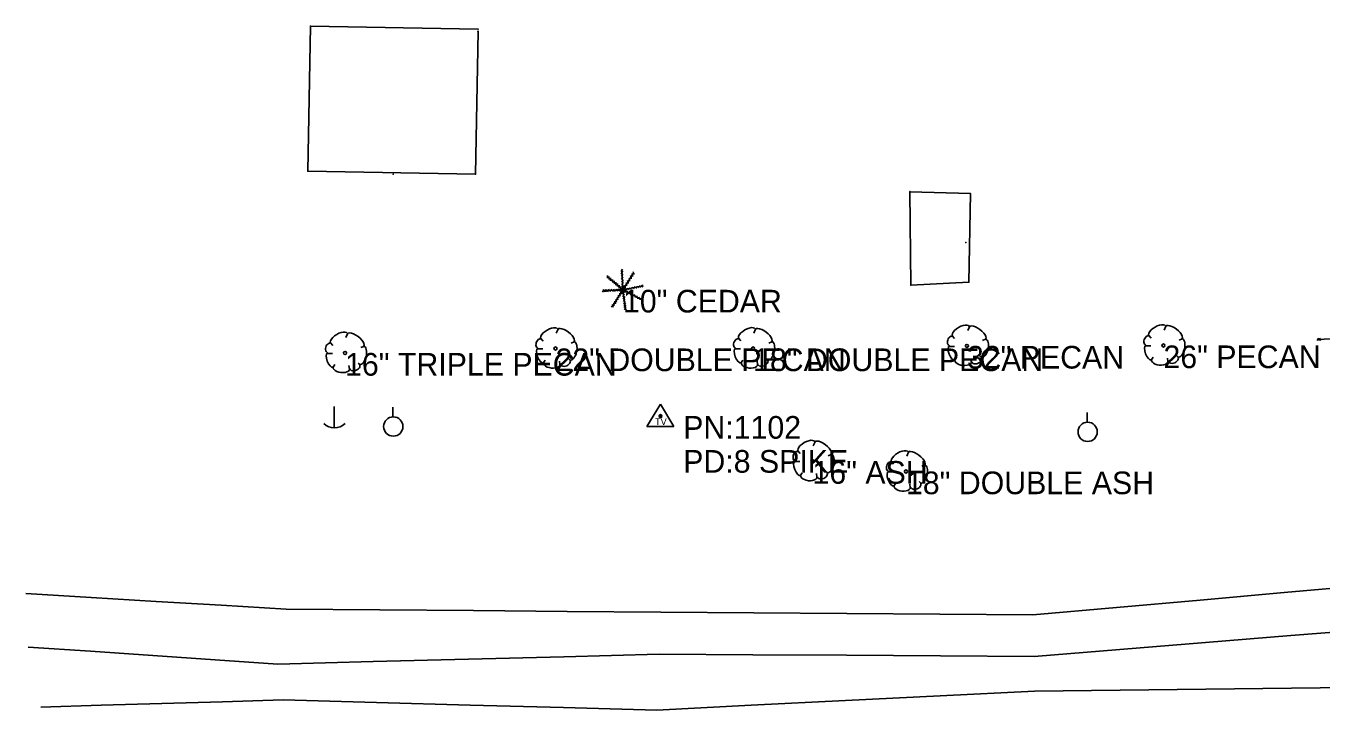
# Model space of a CAD drawing. Extents: x 1930288 to 1941089, y 588389 to 611475.
# Drawn here: x 1930358.9 to 1930644.9, y 598182.4 to 598333.3 of the extents above; entities that cross this region are included whole.
import ezdxf

# ---------------------------------------------------------------- set-up
doc = ezdxf.new("R2010")
doc.units = 0
for name, color, linetype in [('S_BUILDING', 7, 'Continuous'), ('S_DITCHLINE', 7, 'Continuous'), ('S_MSC_PT_SYM', 7, 'Continuous'), ('S_SECONDARY_CTL', 7, 'Continuous'), ('S_SECONDARY_CTL_ANNOT', 7, 'Continuous'), ('S_STR_PT_SYM', 7, 'Continuous'), ('S_STREAM', 7, 'Continuous'), ('S_TREE', 7, 'Continuous'), ('S_TREE_ANNOT', 7, 'Continuous'), ('S_UTILITY_POLE', 7, 'Continuous')]:
    doc.layers.add(name, color=color, linetype=linetype)

msp = doc.modelspace()

# ---------------------------------------------------------------- linework, layer by layer
at = {"layer": 'S_BUILDING'}
for p, q in [((1930421.19, 598301.28), (1930421.76, 598333.27)), ((1930421.76, 598333.27), (1930458.76, 598332.62)), ((1930458.75, 598332.12), (1930458.19, 598300.62)), ((1930458.19, 598300.62), (1930421.19, 598301.28)), ((1930567.44, 598296.33), (1930554.09, 598296.75)), ((1930554.09, 598296.75), (1930554.28, 598276.12)), ((1930567.08, 598276.78), (1930567.44, 598296.33)), ((1930554.28, 598276.12), (1930567.08, 598276.78))]:
    msp.add_line(p, q, dxfattribs=at)
at = {"layer": 'S_DITCHLINE'}
msp.add_lwpolyline([(1930657.08, 598200.36), (1930638.19, 598198.83), (1930619.3, 598197.31), (1930600.42, 598195.78), (1930581.53, 598194.26), (1930560.82, 598194.37), (1930540.12, 598194.49), (1930519.42, 598194.6), (1930498.71, 598194.71), (1930477.66, 598194.18), (1930456.61, 598193.64), (1930435.57, 598193.1), (1930414.52, 598192.57), (1930400.74, 598193.5), (1930386.97, 598194.44), (1930373.2, 598195.37), (1930359.42, 598196.3)], dxfattribs=at)
at = {"layer": 'S_MSC_PT_SYM'}
for points in [[(1930440.04, 598300.62), (1930440.04, 598300.67), (1930440.04, 598300.62), (1930439.99, 598300.62), (1930440.04, 598300.62), (1930440.04, 598300.57), (1930440.04, 598300.62), (1930440.09, 598300.62)], [(1930566.44, 598285.55), (1930566.44, 598285.6), (1930566.44, 598285.55), (1930566.39, 598285.55), (1930566.44, 598285.55), (1930566.44, 598285.5), (1930566.44, 598285.55), (1930566.49, 598285.55)]]:
    msp.add_lwpolyline(points, dxfattribs=at)
at = {"layer": 'S_SECONDARY_CTL'}
for p, q in [((1930499.04, 598249.88), (1930496.03, 598244.93)), ((1930499.04, 598249.88), (1930501.98, 598244.93)), ((1930496.03, 598244.93), (1930501.98, 598244.93))]:
    msp.add_line(p, q, dxfattribs=at)
for radius in [0.311, 0.183, 0.103]:
    msp.add_circle((1930499.04, 598247.27), radius, dxfattribs=at)
at = {"layer": 'S_STR_PT_SYM'}
for points in [[(1930421.76, 598333.27), (1930421.76, 598333.32), (1930421.76, 598333.27), (1930421.71, 598333.27), (1930421.76, 598333.27), (1930421.76, 598333.22), (1930421.76, 598333.27), (1930421.81, 598333.27)], [(1930458.75, 598332.12), (1930458.75, 598332.17), (1930458.75, 598332.12), (1930458.7, 598332.12), (1930458.75, 598332.12), (1930458.75, 598332.07), (1930458.75, 598332.12), (1930458.8, 598332.12)], [(1930458.76, 598332.62), (1930458.76, 598332.67), (1930458.76, 598332.62), (1930458.71, 598332.62), (1930458.76, 598332.62), (1930458.76, 598332.57), (1930458.76, 598332.62), (1930458.81, 598332.62)], [(1930421.19, 598301.28), (1930421.19, 598301.33), (1930421.19, 598301.28), (1930421.14, 598301.28), (1930421.19, 598301.28), (1930421.19, 598301.23), (1930421.19, 598301.28), (1930421.24, 598301.28)], [(1930458.19, 598300.62), (1930458.19, 598300.67), (1930458.19, 598300.62), (1930458.14, 598300.62), (1930458.19, 598300.62), (1930458.19, 598300.57), (1930458.19, 598300.62), (1930458.24, 598300.62)], [(1930554.09, 598296.75), (1930554.09, 598296.8), (1930554.09, 598296.75), (1930554.04, 598296.75), (1930554.09, 598296.75), (1930554.09, 598296.7), (1930554.09, 598296.75), (1930554.14, 598296.75)], [(1930567.44, 598296.33), (1930567.44, 598296.38), (1930567.44, 598296.33), (1930567.39, 598296.33), (1930567.44, 598296.33), (1930567.44, 598296.28), (1930567.44, 598296.33), (1930567.49, 598296.33)], [(1930554.28, 598276.12), (1930554.28, 598276.17), (1930554.28, 598276.12), (1930554.23, 598276.12), (1930554.28, 598276.12), (1930554.28, 598276.07), (1930554.28, 598276.12), (1930554.33, 598276.12)], [(1930567.08, 598276.78), (1930567.08, 598276.83), (1930567.08, 598276.78), (1930567.03, 598276.78), (1930567.08, 598276.78), (1930567.08, 598276.73), (1930567.08, 598276.78), (1930567.13, 598276.78)]]:
    msp.add_lwpolyline(points, dxfattribs=at)
at = {"layer": 'S_STREAM'}
for points in [[(1930655.17, 598209.99), (1930636.67, 598208.34), (1930618.18, 598206.69), (1930599.68, 598205.04), (1930581.19, 598203.39), (1930560.66, 598203.55), (1930540.14, 598203.72), (1930519.62, 598203.88), (1930499.1, 598204.04), (1930478.42, 598204.19), (1930457.75, 598204.35), (1930437.08, 598204.5), (1930416.41, 598204.66), (1930402.04, 598205.52), (1930387.67, 598206.38), (1930373.31, 598207.25), (1930358.94, 598208.11)], [(1930657.21, 598187.47), (1930638.3, 598187.25), (1930619.39, 598187.04), (1930600.47, 598186.82), (1930581.56, 598186.61), (1930560.73, 598185.56), (1930539.9, 598184.51), (1930519.07, 598183.46), (1930498.24, 598182.41), (1930477.61, 598182.97), (1930456.98, 598183.52), (1930436.34, 598184.08), (1930415.71, 598184.64), (1930402.33, 598184.25), (1930388.96, 598183.86), (1930375.58, 598183.47), (1930362.2, 598183.08)]]:
    msp.add_lwpolyline(points, dxfattribs=at)
at = {"layer": 'S_TREE'}
for p, q in [((1930487.46, 598277.85), (1930487.16, 598277.81)), ((1930490.74, 598275.11), (1930487.28, 598278.02)), ((1930487.32, 598277.99), (1930487.32, 598278.29)), ((1930487.63, 598277.74), (1930487.63, 598278.04)), ((1930487.99, 598277.45), (1930487.99, 598277.75)), ((1930490.49, 598279.19), (1930490.26, 598279.39)), ((1930490.52, 598278.63), (1930490.29, 598278.82)), ((1930490.55, 598278.05), (1930490.32, 598278.25)), ((1930490.74, 598275.11), (1930490.47, 598279.55)), ((1930490.48, 598279.44), (1930490.67, 598279.67)), ((1930490.51, 598278.96), (1930490.7, 598279.19)), ((1930490.55, 598278.36), (1930490.73, 598278.59)), ((1930490.58, 598277.65), (1930490.77, 598277.88)), ((1930490.74, 598275.11), (1930493.08, 598278.79)), ((1930492.22, 598277.45), (1930492.13, 598277.74)), ((1930492.38, 598277.66), (1930492.68, 598277.71)), ((1930492.52, 598277.97), (1930492.43, 598278.25)), ((1930492.7, 598278.16), (1930493, 598278.2)), ((1930492.81, 598278.42), (1930492.72, 598278.71)), ((1930492.95, 598278.58), (1930493.25, 598278.62)), ((1930493.06, 598278.76), (1930492.97, 598279.05)), ((1930486.37, 598274.9), (1930486.24, 598274.63)), ((1930490.74, 598275.11), (1930486.29, 598274.9)), ((1930486.52, 598274.92), (1930486.35, 598275.17)), ((1930486.72, 598274.92), (1930486.59, 598274.65)), ((1930486.91, 598274.95), (1930486.74, 598275.19)), ((1930487.06, 598274.94), (1930486.93, 598274.67)), ((1930487.31, 598274.95), (1930487.14, 598275.19)), ((1930487.48, 598274.96), (1930487.35, 598274.69)), ((1930487.81, 598277.57), (1930487.51, 598277.55)), ((1930487.71, 598274.97), (1930487.54, 598275.22)), ((1930487.99, 598274.98), (1930487.86, 598274.71)), ((1930488.17, 598277.25), (1930487.87, 598277.23)), ((1930488.28, 598274.99), (1930488.11, 598275.23)), ((1930488.63, 598276.88), (1930488.33, 598276.85)), ((1930490.74, 598275.11), (1930488.36, 598271.34)), ((1930488.4, 598277.09), (1930488.4, 598277.39)), ((1930488.55, 598275.01), (1930488.42, 598274.74)), ((1930488.83, 598275.02), (1930488.66, 598275.27)), ((1930488.99, 598276.55), (1930488.69, 598276.52)), ((1930488.81, 598276.76), (1930488.81, 598277.06)), ((1930489.04, 598275.03), (1930488.9, 598274.76)), ((1930489.32, 598276.28), (1930489.02, 598276.26)), ((1930489.14, 598276.48), (1930489.14, 598276.78)), ((1930489.31, 598275.04), (1930489.14, 598275.28)), ((1930489.66, 598275.99), (1930489.37, 598275.96)), ((1930489.51, 598275.05), (1930489.38, 598274.78)), ((1930489.5, 598276.17), (1930489.5, 598276.47)), ((1930489.75, 598275.08), (1930489.58, 598275.32)), ((1930490.03, 598275.69), (1930489.73, 598275.67)), ((1930489.97, 598275.06), (1930489.83, 598274.79)), ((1930489.87, 598275.87), (1930489.87, 598276.17)), ((1930490.08, 598275.11), (1930489.92, 598275.36)), ((1930490.39, 598275.39), (1930490.09, 598275.37)), ((1930490.35, 598275.07), (1930490.22, 598274.8)), ((1930490.23, 598275.56), (1930490.23, 598275.86)), ((1930490.57, 598277.39), (1930490.35, 598277.59)), ((1930490.61, 598276.8), (1930490.39, 598277)), ((1930490.65, 598276.23), (1930490.43, 598276.43)), ((1930490.66, 598275.61), (1930490.44, 598275.81)), ((1930490.65, 598277.08), (1930490.84, 598277.32)), ((1930490.66, 598276.51), (1930490.85, 598276.75)), ((1930490.69, 598275.84), (1930490.88, 598276.08)), ((1930490.74, 598275.11), (1930495.16, 598275.98)), ((1930490.74, 598275.11), (1930494.66, 598273.06)), ((1930490.74, 598275.11), (1930491.27, 598270.74)), ((1930491.07, 598274.93), (1930491.34, 598275.07)), ((1930491.09, 598275.6), (1930491.39, 598275.64)), ((1930491.19, 598275.86), (1930491.1, 598276.15)), ((1930491.12, 598275.19), (1930491.32, 598275.42)), ((1930491.25, 598274.83), (1930491.32, 598274.54)), ((1930491.36, 598275.23), (1930491.61, 598275.07)), ((1930491.37, 598276.06), (1930491.67, 598276.11)), ((1930491.55, 598276.39), (1930491.46, 598276.68)), ((1930491.52, 598275.25), (1930491.72, 598275.47)), ((1930491.55, 598274.7), (1930491.81, 598274.84)), ((1930491.71, 598276.61), (1930492.01, 598276.65)), ((1930491.85, 598276.88), (1930491.76, 598277.17)), ((1930491.88, 598275.3), (1930492.13, 598275.14)), ((1930492.05, 598275.36), (1930492.25, 598275.58)), ((1930492.06, 598277.12), (1930492.35, 598277.17)), ((1930492.39, 598275.42), (1930492.65, 598275.26)), ((1930492.62, 598275.49), (1930492.82, 598275.71)), ((1930493, 598275.55), (1930493.25, 598275.39)), ((1930493.25, 598275.63), (1930493.45, 598275.85)), ((1930493.58, 598275.65), (1930493.83, 598275.49)), ((1930493.84, 598275.72), (1930494.04, 598275.94)), ((1930494.09, 598275.77), (1930494.34, 598275.61)), ((1930494.33, 598275.82), (1930494.53, 598276.04)), ((1930494.52, 598275.86), (1930494.77, 598275.7)), ((1930494.77, 598275.91), (1930494.97, 598276.13)), ((1930494.92, 598275.92), (1930495.18, 598275.76)), ((1930495, 598275.96), (1930495.2, 598276.18)), ((1930488.85, 598272.14), (1930488.55, 598272.1)), ((1930489.08, 598272.51), (1930488.79, 598272.48)), ((1930489, 598272.33), (1930489.08, 598272.04)), ((1930489.38, 598272.96), (1930489.08, 598272.93)), ((1930489.25, 598272.71), (1930489.32, 598272.42)), ((1930489.65, 598273.38), (1930489.35, 598273.35)), ((1930489.53, 598273.17), (1930489.6, 598272.88)), ((1930489.9, 598273.8), (1930489.6, 598273.77)), ((1930489.79, 598273.6), (1930489.86, 598273.31)), ((1930490.17, 598274.25), (1930489.88, 598274.21)), ((1930490.05, 598274.01), (1930490.12, 598273.72)), ((1930490.41, 598274.61), (1930490.11, 598274.58)), ((1930490.32, 598274.45), (1930490.4, 598274.16)), ((1930490.54, 598274.79), (1930490.61, 598274.5)), ((1930490.8, 598274.43), (1930490.61, 598274.21)), ((1930490.87, 598273.85), (1930490.67, 598273.63)), ((1930490.95, 598273.29), (1930490.76, 598273.06)), ((1930490.82, 598274.68), (1930491.08, 598274.53)), ((1930491.02, 598272.72), (1930490.83, 598272.5)), ((1930490.86, 598274.13), (1930491.11, 598273.97)), ((1930491.09, 598272.27), (1930490.89, 598272.04)), ((1930490.94, 598273.56), (1930491.2, 598273.41)), ((1930491.01, 598273.01), (1930491.26, 598272.86)), ((1930491.08, 598272.5), (1930491.33, 598272.35)), ((1930491.11, 598272.07), (1930491.37, 598271.92)), ((1930491.83, 598274.53), (1930491.9, 598274.24)), ((1930492.1, 598274.4), (1930492.37, 598274.54)), ((1930492.37, 598274.25), (1930492.44, 598273.96)), ((1930492.66, 598274.12), (1930492.92, 598274.26)), ((1930492.89, 598273.98), (1930492.96, 598273.69)), ((1930493.14, 598273.86), (1930493.41, 598274)), ((1930493.43, 598273.68), (1930493.5, 598273.39)), ((1930493.68, 598273.59), (1930493.94, 598273.73)), ((1930493.94, 598273.43), (1930494.01, 598273.13)), ((1930494.23, 598273.31), (1930494.49, 598273.45)), ((1930494.43, 598273.17), (1930494.5, 598272.88)), ((1930494.62, 598273.1), (1930494.88, 598273.24)), ((1930488.39, 598271.42), (1930488.1, 598271.39)), ((1930488.59, 598271.72), (1930488.3, 598271.69)), ((1930488.52, 598271.58), (1930488.59, 598271.29)), ((1930488.74, 598271.93), (1930488.82, 598271.64)), ((1930491.13, 598271.89), (1930490.93, 598271.66)), ((1930491.18, 598271.44), (1930490.99, 598271.21)), ((1930491.23, 598271.02), (1930491.03, 598270.79)), ((1930491.15, 598271.66), (1930491.41, 598271.51)), ((1930491.22, 598271.2), (1930491.48, 598271.04)), ((1930491.26, 598270.86), (1930491.51, 598270.7)), ((1930476.4, 598266.41), (1930476.01, 598265.56)), ((1930520.03, 598266.42), (1930519.64, 598265.57)), ((1930567.23, 598266.98), (1930566.84, 598266.13)), ((1930610.6, 598267.07), (1930610.22, 598266.22)), ((1930426.15, 598263.41), (1930426.66, 598262.83)), ((1930429.95, 598265.43), (1930429.56, 598264.58)), ((1930472.6, 598264.4), (1930473.1, 598263.82)), ((1930479.96, 598263.62), (1930479.3, 598263.35)), ((1930516.23, 598264.41), (1930516.74, 598263.83)), ((1930523.6, 598263.63), (1930522.94, 598263.36)), ((1930563.43, 598264.97), (1930563.93, 598264.38)), ((1930570.79, 598264.19), (1930570.13, 598263.92)), ((1930606.81, 598265.06), (1930607.31, 598264.48)), ((1930614.17, 598264.28), (1930613.51, 598264.01)), ((1930644.12, 598264.18), (1930643.99, 598263.91)), ((1930648.49, 598264.39), (1930644.04, 598264.18)), ((1930644.27, 598264.2), (1930644.1, 598264.45)), ((1930644.47, 598264.2), (1930644.34, 598263.93)), ((1930644.66, 598264.22), (1930644.49, 598264.47)), ((1930644.81, 598264.22), (1930644.68, 598263.95)), ((1930425.49, 598261.09), (1930426.62, 598261.09)), ((1930433.51, 598262.64), (1930432.86, 598262.37)), ((1930471.94, 598262.07), (1930473.06, 598262.07)), ((1930515.57, 598262.08), (1930516.7, 598262.08)), ((1930562.77, 598262.64), (1930563.89, 598262.64)), ((1930570.02, 598260.08), (1930569.55, 598260.51)), ((1930606.15, 598262.73), (1930607.27, 598262.73)), ((1930613.39, 598260.18), (1930612.93, 598260.6)), ((1930426.66, 598257.91), (1930427.12, 598258.61)), ((1930430.34, 598257.64), (1930430.26, 598258.41)), ((1930432.74, 598258.53), (1930432.27, 598258.96)), ((1930473.1, 598258.9), (1930473.57, 598259.59)), ((1930476.78, 598258.63), (1930476.71, 598259.4)), ((1930479.19, 598259.52), (1930478.72, 598259.94)), ((1930516.74, 598258.9), (1930517.2, 598259.6)), ((1930520.42, 598258.63), (1930520.34, 598259.41)), ((1930522.82, 598259.52), (1930522.36, 598259.95)), ((1930563.93, 598259.46), (1930564.4, 598260.16)), ((1930567.61, 598259.19), (1930567.54, 598259.97)), ((1930607.31, 598259.56), (1930607.78, 598260.25)), ((1930610.99, 598259.28), (1930610.91, 598260.06)), ((1930533.14, 598241.57), (1930532.75, 598240.72)), ((1930529.34, 598239.56), (1930529.85, 598238.98)), ((1930536.71, 598238.78), (1930536.05, 598238.51)), ((1930553.77, 598239.28), (1930553.38, 598238.43)), ((1930528.68, 598237.23), (1930529.81, 598237.23)), ((1930535.93, 598234.68), (1930535.47, 598235.1)), ((1930549.32, 598234.94), (1930550.44, 598234.94)), ((1930549.97, 598237.26), (1930550.48, 598236.68)), ((1930557.34, 598236.49), (1930556.68, 598236.22)), ((1930529.85, 598234.06), (1930530.31, 598234.75)), ((1930533.53, 598233.78), (1930533.45, 598234.56)), ((1930550.48, 598231.76), (1930550.94, 598232.46)), ((1930554.16, 598231.49), (1930554.08, 598232.26)), ((1930556.56, 598232.38), (1930556.1, 598232.81))]:
    msp.add_line(p, q, dxfattribs=at)
for centre in [(1930429.39, 598261.18), (1930475.84, 598262.17), (1930519.47, 598262.18), (1930566.67, 598262.74), (1930610.05, 598262.83), (1930532.58, 598237.33), (1930553.21, 598235.03)]:
    msp.add_circle(centre, 0.341, dxfattribs=at)
for centre, major_axis, ratio, start_param, end_param in [((1930474.5, 598265.37), (1.86, 1.08), 0.471018, 0, 3.141593), ((1930478.16, 598265.05), (-1.81, 1.36), 0.405113, 3.141593, 6.283186), ((1930518.14, 598265.38), (1.86, 1.08), 0.471018, 0, 3.141593), ((1930521.79, 598265.06), (-1.81, 1.36), 0.405113, 3.141593, 6.283186), ((1930565.33, 598265.94), (1.86, 1.08), 0.471018, 0, 3.141593), ((1930568.99, 598265.61), (-1.81, 1.36), 0.405113, 3.141593, 6.283186), ((1930608.71, 598266.03), (1.86, 1.08), 0.471018, 0, 3.141593), ((1930612.36, 598265.71), (-1.81, 1.36), 0.405113, 3.141593, 6.283186), ((1930425.82, 598262.27), (0.31, 1.03), 0.646762, 0, 3.141593), ((1930428.05, 598264.39), (1.86, 1.08), 0.471018, 0, 3.141593), ((1930431.71, 598264.06), (-1.81, 1.36), 0.405113, 3.141593, 6.283186), ((1930472.27, 598263.26), (0.31, 1.03), 0.646762, 0, 3.141593), ((1930479.51, 598261.64), (0.46, 2.04), 0.482994, 3.141593, 6.283185), ((1930515.9, 598263.26), (0.31, 1.03), 0.646762, 0, 3.141593), ((1930523.15, 598261.65), (0.46, 2.04), 0.482994, 3.141593, 6.283185), ((1930563.1, 598263.82), (0.31, 1.03), 0.646762, 0, 3.141593), ((1930570.34, 598262.21), (0.46, 2.04), 0.482994, 3.141593, 6.283185), ((1930606.48, 598263.92), (0.31, 1.03), 0.646762, 0, 3.141593), ((1930613.72, 598262.3), (0.46, 2.04), 0.482994, 3.141593, 6.283185), ((1930426.13, 598259.62), (-0.61, 1.6), 0.420543, 6.283185, 9.424777), ((1930433.06, 598260.65), (0.46, 2.04), 0.482994, 3.141593, 6.283185), ((1930472.57, 598260.61), (-0.61, 1.6), 0.420543, 6.283185, 9.424777), ((1930516.21, 598260.61), (-0.61, 1.6), 0.420543, 6.283185, 9.424777), ((1930563.4, 598261.17), (-0.61, 1.6), 0.420543, 6.283185, 9.424777), ((1930606.78, 598261.27), (-0.61, 1.6), 0.420543, 6.283185, 9.424777), ((1930428.59, 598257.84), (-1.83, 0.19), 0.529943, 0, 3.141593), ((1930431.54, 598258.13), (1.09, 0.46), 0.711534, 3.141592, 6.283185), ((1930475.03, 598258.83), (-1.83, 0.19), 0.529943, 0, 3.141593), ((1930477.99, 598259.12), (1.09, 0.46), 0.711534, 3.141592, 6.283185), ((1930518.67, 598258.83), (-1.83, 0.19), 0.529943, 0, 3.141593), ((1930521.62, 598259.13), (1.09, 0.46), 0.711534, 3.141592, 6.283185), ((1930565.86, 598259.39), (-1.83, 0.19), 0.529943, 0, 3.141593), ((1930568.82, 598259.68), (1.09, 0.46), 0.711534, 3.141592, 6.283185), ((1930609.24, 598259.48), (-1.83, 0.19), 0.529943, 0, 3.141593), ((1930612.2, 598259.78), (1.09, 0.46), 0.711534, 3.141592, 6.283185), ((1930531.25, 598240.53), (1.86, 1.08), 0.471018, 0, 3.141593), ((1930534.9, 598240.21), (-1.81, 1.36), 0.405113, 3.141593, 6.283186), ((1930529.01, 598238.42), (0.31, 1.03), 0.646762, 0, 3.141593), ((1930536.26, 598236.8), (0.46, 2.04), 0.482994, 3.141593, 6.283185), ((1930551.88, 598238.23), (1.86, 1.08), 0.471018, 0, 3.141593), ((1930555.53, 598237.91), (-1.81, 1.36), 0.405113, 3.141593, 6.283186), ((1930529.32, 598235.76), (-0.61, 1.6), 0.420543, 6.283185, 9.424777), ((1930549.64, 598236.12), (0.31, 1.03), 0.646762, 0, 3.141593), ((1930549.95, 598233.47), (-0.61, 1.6), 0.420543, 6.283185, 9.424777), ((1930556.89, 598234.5), (0.46, 2.04), 0.482994, 3.141593, 6.283185), ((1930531.78, 598233.98), (-1.83, 0.19), 0.529943, 0, 3.141593), ((1930534.74, 598234.28), (1.09, 0.46), 0.711534, 3.141592, 6.283185), ((1930555.37, 598231.98), (1.09, 0.46), 0.711534, 3.141592, 6.283185), ((1930552.41, 598231.69), (-1.83, 0.19), 0.529943, 0, 3.141593)]:
    msp.add_ellipse(centre, major_axis=major_axis, ratio=ratio, start_param=start_param, end_param=end_param, dxfattribs=at)
at = {"layer": 'S_UTILITY_POLE'}
for p, q in [((1930426.97, 598249.36), (1930426.97, 598244.63)), ((1930439.92, 598247.1), (1930439.92, 598249.21)), ((1930593.2, 598245.93), (1930593.2, 598248.03))]:
    msp.add_line(p, q, dxfattribs=at)
for centre in [(1930440.04, 598244.96), (1930593.32, 598243.78)]:
    msp.add_circle(centre, 2.13, dxfattribs=at)
msp.add_arc((1930427.03, 598248.06), 3.41, 226.3972, 313.6028, dxfattribs=at)

# ---------------------------------------------------------------- texts
at = {"layer": 'S_SECONDARY_CTL'}
msp.add_text('TV', height=1.5, rotation=360, dxfattribs=at).set_placement((1930497.83, 598245.26))
at = {"layer": 'S_SECONDARY_CTL_ANNOT'}
for s, p in [('PN:1102', (1930504.04, 598242.27)), ('PD:8 SPIKE', (1930504.04, 598234.77))]:
    msp.add_text(s, height=5, dxfattribs=at).set_placement(p)
at = {"layer": 'S_TREE_ANNOT'}
for s, p in [('10" CEDAR', (1930490.74, 598270.11)), ('16" TRIPLE PECAN', (1930429.39, 598256.18)), ('22" DOUBLE PECAN', (1930475.84, 598257.17)), ('18" DOUBLE PECAN', (1930519.47, 598257.18)), ('32" PECAN', (1930566.67, 598257.74)), ('26" PECAN', (1930610.05, 598257.83)), ('16" ASH', (1930532.58, 598232.33)), ('18" DOUBLE ASH', (1930553.21, 598230.03))]:
    msp.add_text(s, height=5, dxfattribs=at).set_placement(p)

doc.saveas('drawing.dxf')
